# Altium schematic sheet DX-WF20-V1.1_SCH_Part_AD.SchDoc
size A4
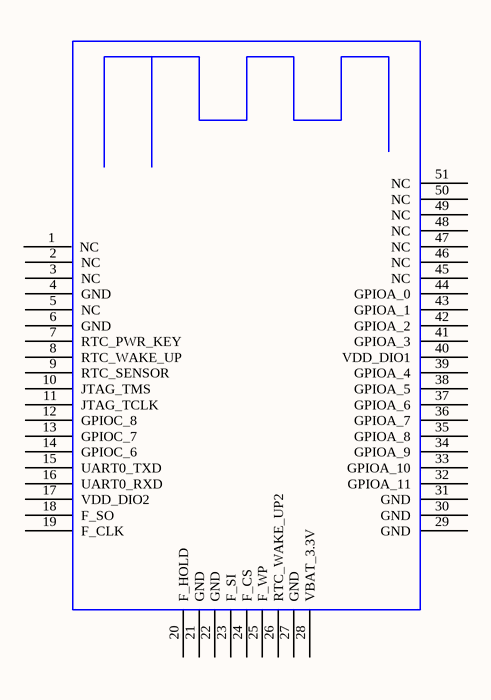
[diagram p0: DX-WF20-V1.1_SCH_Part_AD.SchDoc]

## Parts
?  (no value)  [DX-WF20]

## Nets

Not connected (* = marked no-connect by the designer): ? 1(NC) 2(NC) 3(NC) 4(GND) 5(NC) 6(GND) 7(RTC_PWR_KEY) 8(RTC_WAKE_UP) 9(RTC_SENSOR) 10(JTAG_TMS) 11(JTAG_TCLK) 12(GPIOC_8) 13(GPIOC_7) 14(GPIOC_6) 15(UART0_TXD) 16(UART0_RXD) 17(VDD_DIO2) 18(F_SO) 19(F_CLK) 20(F_HOLD) 21(GND) 22(GND) 23(F_SI) 24(F_CS) 25(F_WP) 26(RTC_WAKE_UP2) 27(GND) 28(VBAT_3.3V) 29(GND) 30(GND) 31(GND) 32(GPIOA_11) 33(GPIOA_10) 34(GPIOA_9) 35(GPIOA_8) 36(GPIOA_7) 37(GPIOA_6) 38(GPIOA_5) 39(GPIOA_4) 40(VDD_DIO1) 41(GPIOA_3) 42(GPIOA_2) 43(GPIOA_1) 44(GPIOA_0) 45(NC) 46(NC) 47(NC) 48(NC) 49(NC) 50(NC) 51(NC)

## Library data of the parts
? = Component_1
